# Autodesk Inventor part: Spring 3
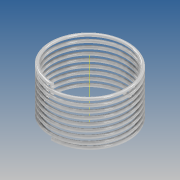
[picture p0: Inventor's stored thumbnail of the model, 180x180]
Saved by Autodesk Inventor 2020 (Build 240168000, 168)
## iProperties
Created: 2019-10
Part Number: Spring 3
Material: Generic
Document SubType Name: Modeling
Designer: yello
Density: 1 g/cm^3
Appearance: Default
Author: yello
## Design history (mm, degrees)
sketch "Sketch1"
  geometry: L1 (0, 0)-(8, 0); L2 (0, 0)-(0, 3.1); C1 r 0.125 at (0, 3.1)
  constraints: 4 end point, 1 centre point, 1 coincident, 1 horizontal, 1 vertical
  dimensions: "d0" = 8 distance of L1.start L1.end; "d1" = 3.1 distance of L1.start L2.end; "d2" = 0.25 diameter of C1
coil "Coil1" sketch "Sketch1" pitch "d3" = 0.45; turns "d5" = 8.5; dims "d4" = 10, "d6" = 0, angle "d7" = 90 deg, angle "d8" = 90 deg, "d9" = 0, "d10" = 0
body "Solid1"
